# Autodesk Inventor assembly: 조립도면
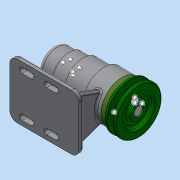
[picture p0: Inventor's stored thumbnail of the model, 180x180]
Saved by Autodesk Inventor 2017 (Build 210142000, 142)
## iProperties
Part Number: 조립도면
Material: 일반
Document SubType Name: Assembly
Designer: MRC
Author: MRC
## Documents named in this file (12)
- C:\Users\MRC\Desktop\조립도면.iam
- C:\Users\MRC\Desktop\부품1.ipt
- C:\Users\MRC\Desktop\711009V1006\V벨트풀리.ipt
- C:\Users\MRC\Desktop\711009V1006\멈춤나사 M3.ipt
- C:\Users\MRC\Desktop\711009V1006\베어링 6004.ipt
- C:\Users\MRC\Desktop\711009V1006\베어링 51202.ipt
- C:\Users\MRC\Desktop\711009V1006\볼트 M4.ipt
- C:\Users\MRC\Desktop\711009V1006\어댑터슬리브.ipt
- C:\Users\MRC\Desktop\711009V1006\오일 실 20x35x7.ipt
- C:\Users\MRC\Desktop\711009V1006\축.ipt
- C:\Users\MRC\Desktop\711009V1006\커버.ipt
- C:\Users\MRC\Desktop\711009V1006\키 5x5.ipt
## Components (1 placed, 1 different names)
1. V벨트풀리:1
